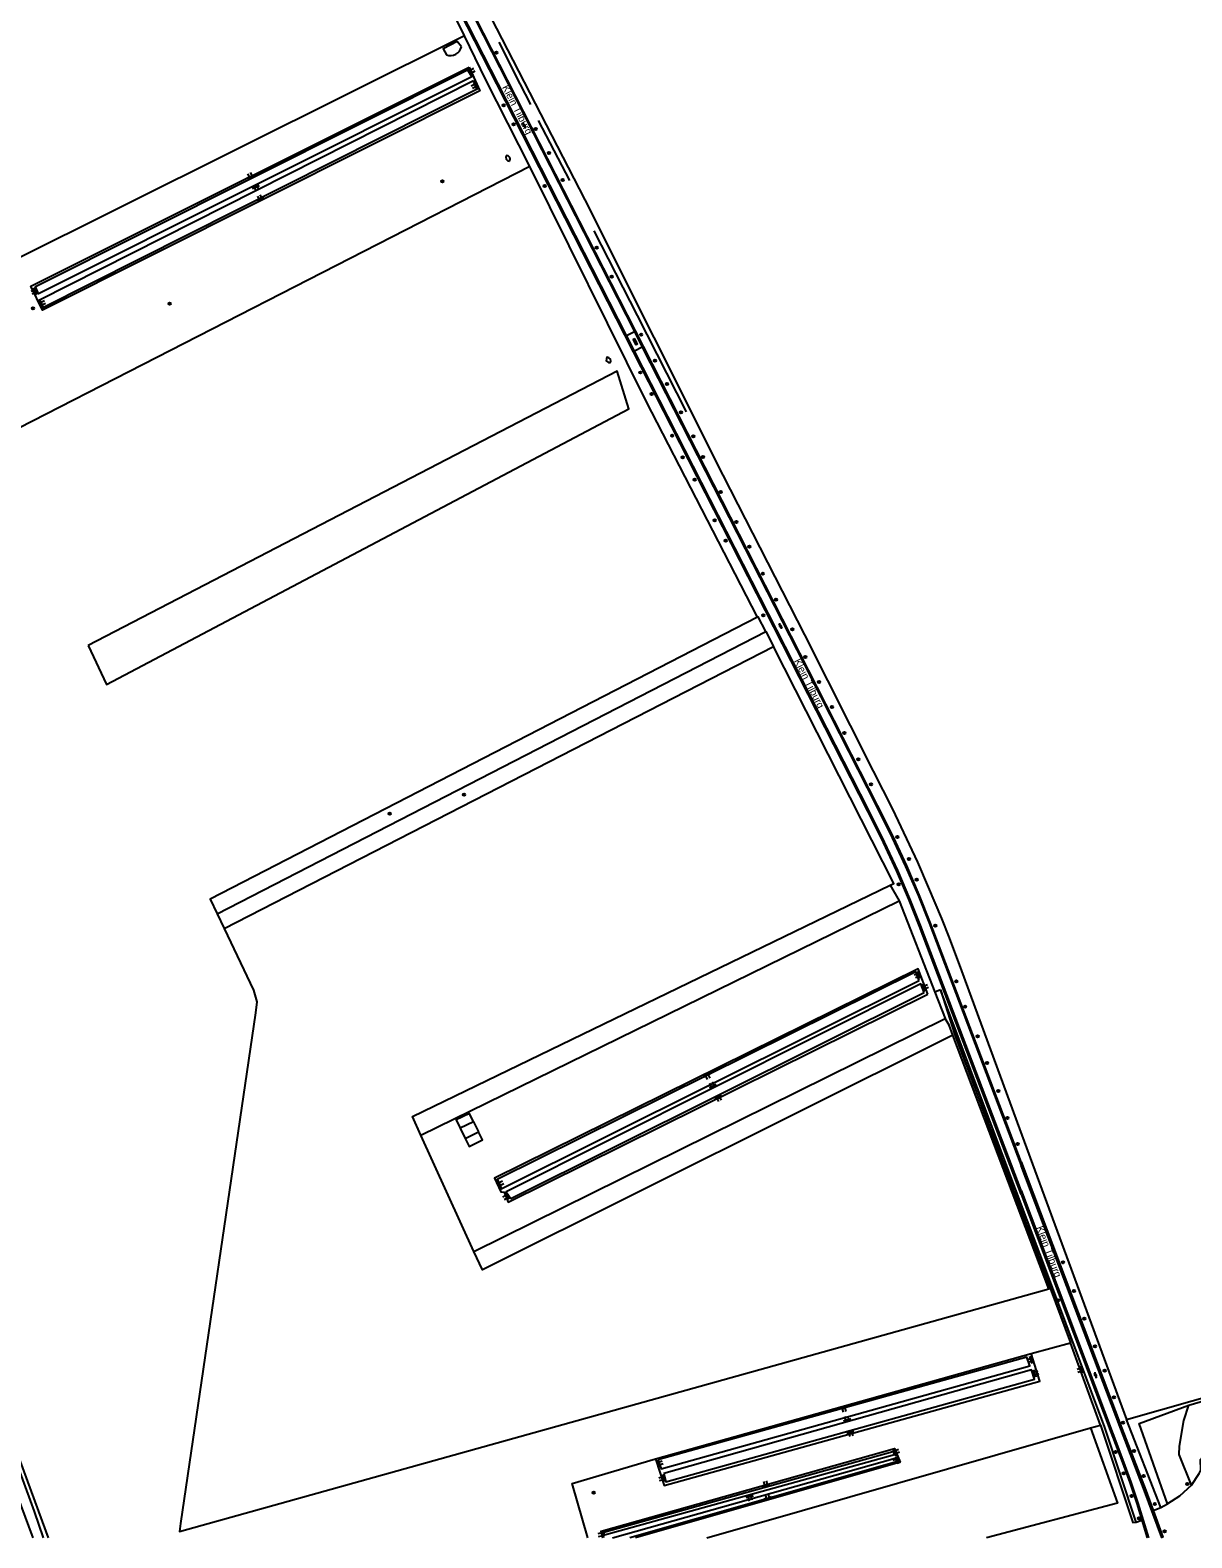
# Model space of a CAD drawing. Extents: x 124000 to 129000, y 395500 to 397503.
# Drawn here: x 126659 to 127059, y 395500 to 396018 of the extents above; entities that cross this region are included whole.
import ezdxf

# ---------------------------------------------------------------- set-up
doc = ezdxf.new("R2010")
doc.units = 0
for name, color, linetype in [('gg-afsc-draadraster', 7, 'Continuous'), ('gg-anno-openbare ruimte label', 7, 'Continuous'), ('gg-bbg-bijgebouw', 7, 'Continuous'), ('gg-bbg-luifel en loopbrug', 7, 'Continuous'), ('gg-knt-bovenkant onderkant talud', 7, 'Continuous'), ('gg-knt-verharding', 7, 'Continuous'), ('gg-kntw-bovenkant insteek waterloop', 7, 'Continuous'), ('gg-kntw-midden sloot', 7, 'Continuous'), ('gg-kntw-waterlijn', 7, 'Continuous'), ('gt-grn-groengrens', 7, 'Continuous'), ('gt-grn-groengrens NZ', 7, 'Continuous'), ('gt-grn-weggrens', 7, 'Continuous'), ('gt-symb-boom', 7, 'Continuous'), ('gt-symb-gesloten verharding', 7, 'Continuous'), ('gt-symb-klinker verharding', 7, 'Continuous'), ('gt-symb-talud symbool', 7, 'Continuous')]:
    doc.layers.add(name, color=color, linetype=linetype)

# ---------------------------------------------------------------- blocks, each defined once
blk = doc.blocks.new('gt0-BOOM')
at = {"layer": 'gt-symb-boom'}
for radius in [0.4, 0.2]:
    blk.add_circle((0, 0), radius, dxfattribs=at)
blk = doc.blocks.new('gt0-TALUD_1')
at = {"layer": 'gt-symb-talud symbool'}
for p, q in [((-1, -1), (-1, 0)), ((-0.5, -2), (-0.5, 0)), ((0, -1), (0, 0)), ((0.5, -2), (0.5, 0)), ((1, -1), (1, 0))]:
    blk.add_line(p, q, dxfattribs=at)
blk = doc.blocks.new('gt0-GESVH1')
at = {"layer": 'gt-symb-gesloten verharding'}
for p, q in [((-0.99, -0.26), (0.01, 0.24)), ((0.01, -0.26), (-0.99, 0.24)), ((0.01, 0.24), (1.01, -0.26)), ((1.01, 0.24), (0.01, -0.26))]:
    blk.add_line(p, q, dxfattribs=at)
blk = doc.blocks.new('gt0-KL1')
at = {"layer": 'gt-symb-klinker verharding'}
for p, q in [((-1.15, 0.3), (1.15, 0.3)), ((-1, -0.3), (-1, 0.3)), ((-0.5, 0.3), (-0.5, 0.45)), ((0, -0.3), (0, 0.3)), ((0.5, 0.3), (0.5, 0.45)), ((1, -0.3), (1, 0.3)), ((-1.15, -0.3), (1.15, -0.3)), ((-0.5, -0.45), (-0.5, -0.3)), ((0.5, -0.45), (0.5, -0.3))]:
    blk.add_line(p, q, dxfattribs=at)

msp = doc.modelspace()

# ---------------------------------------------------------------- linework, layer by layer
at = {"layer": 'gg-afsc-draadraster'}
for p, q in [((126726.02, 395709.53), (126914.84, 395806.46)), ((127009.5, 395585.57), (126976.53, 395672.83)), ((126811.92, 395598.36), (126793.63, 395638.4)), ((127036.25, 395540.67), (127076.4, 395552.07))]:
    msp.add_line(p, q, dxfattribs=at)
for points in [[(126954.95, 395724.35), (126956.26, 395724.99), (126914.84, 395806.46)], [(126793.63, 395638.4), (126790.8, 395644.81), (126954.95, 395724.35)], [(126726.02, 395709.53), (126736.15, 395688.3), (126737.27, 395684.29), (126736.88, 395680.43), (126711.09, 395504.92), (126710.75, 395502.07), (127009.5, 395585.57)], [(126976.53, 395672.83), (126814.87, 395592.14), (126811.92, 395598.36)]]:
    msp.add_lwpolyline(points, dxfattribs=at)
at = {"layer": 'gg-bbg-bijgebouw'}
for p, q in [((126811.81, 395643.05), (126807.22, 395640.8)), ((126808.94, 395637.3), (126813.53, 395639.55))]:
    msp.add_line(p, q, dxfattribs=at)
for points in [[(126811.81, 395643.05), (126810.44, 395645.84), (126805.82, 395643.65), (126807.22, 395640.8)], [(126808.94, 395637.3), (126810.28, 395634.57), (126814.89, 395636.76), (126813.53, 395639.55)]]:
    msp.add_lwpolyline(points, dxfattribs=at)
at = {"layer": 'gg-bbg-luifel en loopbrug'}
for p, q in [((126811.81, 395643.05), (126813.53, 395639.55)), ((126807.22, 395640.8), (126808.94, 395637.3))]:
    msp.add_line(p, q, dxfattribs=at)
at = {"layer": 'gg-knt-bovenkant onderkant talud'}
for p, q in [((127027.25, 395538.72), (127016.92, 395566.99)), ((126874.27, 395527.09), (127003.43, 395563.28))]:
    msp.add_line(p, q, dxfattribs=at)
for points in [[(126810.25, 396005.71), (126813.99, 395997.49), (126663.62, 395922.06), (126659.57, 395930.41), (126810.25, 396005.71)], [(126809.65, 396004.72), (126811.16, 396002.34), (126662.25, 395927.7), (126661.2, 395930.22), (126809.65, 396004.72)], [(126811.81, 396001.06), (126813, 395998.09), (126663.76, 395922.95), (126662.35, 395925.52), (126811.81, 396001.06)], [(126967.96, 395686.95), (126964.6, 395695.65), (126819, 395623.59), (126821.21, 395618.94), (126822.25, 395618.85), (126823.67, 395615.36), (126967.96, 395686.95)], [(126964.89, 395691.55), (126963.82, 395694.59), (126819.86, 395623.12), (126821.32, 395619.94), (126964.89, 395691.55)], [(126966.71, 395687.42), (126965.52, 395690.46), (126823.03, 395618.96), (126824.58, 395616.59), (126966.71, 395687.42)], [(126972.32, 395688.38), (126977.25, 395672.91), (127009.98, 395585.75)], [(127039.52, 395505.39), (127028.82, 395537.85), (127010.82, 395586), (126972.32, 395688.38)], [(127009.98, 395585.75), (127009.98, 395585.75), (127016.92, 395566.99)], [(126874.27, 395527.09), (126877.27, 395517.98), (127006.42, 395553.86), (127003.43, 395563.28)], [(126875.16, 395526.79), (126876.28, 395523.68), (127002.96, 395559.14), (127001.93, 395562.1), (126875.16, 395526.79)], [(126877.14, 395522.02), (126877.84, 395519.22), (127004.55, 395554.52), (127003.52, 395557.74), (126877.14, 395522.02)], [(127027.25, 395538.72), (127038.42, 395505.21), (127039.52, 395505.39)], [(126856.31, 395500), (126855.62, 395502.29), (126956.47, 395530.72), (126958.38, 395525.91), (126867.44, 395500)], [(126856.74, 395500.82), (126856.51, 395501.87), (126955.92, 395529.64), (126956.42, 395528.49), (126856.74, 395500.82)], [(126859.59, 395500), (126956.69, 395527.31), (126957.19, 395526.11), (126865.53, 395500)]]:
    msp.add_lwpolyline(points, dxfattribs=at)
at = {"layer": 'gg-knt-verharding'}
for p, q in [((126823.63, 396000), (126867.07, 395914.76)), ((126864.32, 395913.35), (126867.07, 395914.76)), ((126867.06, 395907.99), (126864.32, 395913.35)), ((126867.07, 395914.76), (126869.79, 395909.41)), ((126869.79, 395909.41), (126867.06, 395907.99)), ((127041.52, 395505.99), (127043.33, 395500)), ((127048.28, 395500), (127048.3, 395500.01)), ((127048.3, 395500.01), (127048.35, 395500.02)), ((127048.3, 395500.01), (127048.3, 395500))]:
    msp.add_line(p, q, dxfattribs=at)
for points in [[(126703.21, 396235.33), (126720.5, 396201.9), (126732.37, 396178.75), (126801.05, 396044.35), (126823.63, 396000)], [(126870.15, 395909.59), (126801.43, 396044.48), (126720.87, 396202.08)], [(126866.72, 395907.82), (126819.75, 396000), (126794.42, 396049.62), (126770.73, 396095.86), (126742.38, 396151.54)], [(126864.32, 395913.35), (126849.75, 395941.89), (126820.21, 396000), (126794.79, 396049.81), (126771.05, 396096.11), (126742.75, 396151.65)], [(127000, 395618.17), (126965.03, 395710.31), (126961.37, 395719.61), (126957.24, 395729.17), (126952.63, 395739.06), (126947.31, 395749.8), (126879.78, 395882.18), (126866.72, 395907.82)], [(127000, 395619.35), (126965.41, 395710.47), (126961.76, 395719.74), (126957.58, 395729.44), (126953.01, 395739.22), (126947.65, 395750.04), (126867.06, 395907.99)], [(126869.79, 395909.41), (126905.15, 395840.02), (126927.99, 395795.44), (126950.32, 395751.6), (126955.72, 395740.7), (126960.3, 395730.86), (126964.62, 395720.97), (126968.39, 395711.41), (127000, 395628.01)], [(127000, 395629.23), (126968.77, 395711.55), (126965, 395721.1), (126960.7, 395730.98), (126956.08, 395740.87), (126950.68, 395751.78), (126882.29, 395885.77), (126870.15, 395909.59)], [(127000, 395629.23), (127034.62, 395537.57), (127042.8, 395516.21), (127045.33, 395509.32)], [(127048.35, 395500.02), (127042.4, 395516.1), (127034.24, 395537.39), (127000, 395628.01)], [(127000, 395619.35), (127034.84, 395526.86), (127037.68, 395519.14), (127040.12, 395511.86), (127043.82, 395500)], [(127000, 395618.17), (127030.94, 395536.1), (127034.44, 395526.77), (127037.32, 395518.92), (127039.78, 395511.74), (127041.52, 395505.99)], [(127045.33, 395509.32), (127048.71, 395500.15), (127048.35, 395500.02)]]:
    msp.add_lwpolyline(points, dxfattribs=at)
at = {"layer": 'gg-kntw-bovenkant insteek waterloop'}
msp.add_lwpolyline([(126626.44, 395606.28), (126646.15, 395552.5), (126665.56, 395500)], dxfattribs=at)
at = {"layer": 'gg-kntw-midden sloot'}
for p, q in [((126820.5, 396014.31), (126827.7, 396000)), ((126827.7, 396000), (126831.3, 395992.86)), ((126833.96, 395987.35), (126844.8, 395966.73))]:
    msp.add_line(p, q, dxfattribs=at)
msp.add_lwpolyline([(126853.13, 395949.38), (126868.02, 395920.32), (126884.88, 395887.2)], dxfattribs=at)
at = {"layer": 'gg-kntw-waterlijn'}
msp.add_lwpolyline([(126660.4, 395500), (126621.27, 395605.24), (126620.28, 395607.49), (126619.19, 395609.18), (126599.63, 395634.63), (126595.98, 395639.86), (126595.97, 395640.76), (126596.45, 395641.85), (126597.38, 395642.32), (126598.31, 395642.41), (126598.99, 395642.04), (126621.37, 395612.26), (126623.4, 395609.19), (126625.11, 395605.18), (126643.23, 395556.76), (126660.79, 395508.97), (126663.9, 395500)], dxfattribs=at)
at = {"layer": 'gt-grn-groengrens'}
for p, q in [((126808.63, 396016.44), (126651.9, 395938.33)), ((126723.61, 395714.58), (126912.23, 395811.57)), ((126912.23, 395811.57), (126914.84, 395806.46)), ((126954.95, 395724.35), (126958.11, 395718.94)), ((126723.61, 395714.58), (126726.02, 395709.53)), ((126793.63, 395638.4), (126958.11, 395718.94)), ((126958.11, 395718.94), (126970.36, 395687.61)), ((126970.36, 395687.61), (126973.91, 395678.54)), ((126811.92, 395598.36), (126973.91, 395678.54)), ((127003.43, 395563.28), (127016.92, 395566.99)), ((127057.64, 395545.62), (127076.66, 395551.15)), ((126891.93, 395500), (127023.81, 395537.73)), ((127023.81, 395537.73), (127027.25, 395538.72)), ((127048.03, 395510.35), (127036.25, 395540.67)), ((127045.33, 395509.32), (127048.03, 395510.35)), ((127048.03, 395510.35), (127050.33, 395511.62)), ((127039.52, 395505.39), (127041.52, 395505.99))]:
    msp.add_line(p, q, dxfattribs=at)
for points in [[(126747.44, 396158.87), (126804.46, 396048.68), (126849.98, 395960.03), (126897.51, 395865.41), (126925.49, 395810.42), (126949.11, 395763.57), (126955.76, 395750.52), (126964.33, 395732.29), (126968.05, 395723.74), (126972.66, 395712.9), (126975.3, 395706.31), (126979.51, 395694.89), (126999.42, 395640.58), (127036.25, 395540.67)], [(126808.63, 396016.44), (126803.18, 396027.6), (126769.53, 396092.2), (126743.11, 396143.03)], [(126831.14, 395971.52), (126816.04, 396001.3), (126808.63, 396016.44)], [(126807.58, 396012.68), (126806.15, 396014.47), (126801.36, 396012.01), (126802.53, 396009.92)], [(126824.11, 395973.39), (126824.37, 395974.01), (126824.24, 395974.64), (126823.71, 395975.18), (126823.15, 395975.27), (126822.92, 395974.69), (126822.99, 395974.05), (126823.53, 395973.52), (126824.11, 395973.39)], [(126831.14, 395971.52), (126645.72, 395876.57), (126625.28, 395920.24)], [(126909.36, 395816.54), (126871.07, 395890.86), (126831.35, 395971.1), (126831.14, 395971.52)], [(126858.69, 395903.97), (126858.92, 395904.54), (126858.8, 395905.31), (126858.24, 395905.71), (126857.64, 395905.9), (126857.46, 395905.39), (126857.4, 395904.66), (126858.11, 395904.12), (126858.69, 395903.97)], [(126679.37, 395806.78), (126685.61, 395793.43), (126865.19, 395888.16), (126861.17, 395901.1), (126679.37, 395806.78)], [(126909.36, 395816.54), (126721.2, 395719.62), (126723.61, 395714.58)], [(126912.23, 395811.57), (126909.62, 395816.67), (126909.36, 395816.54)], [(126976.53, 395672.83), (126975.28, 395676.22), (126973.91, 395678.54)], [(127050.33, 395511.62), (127040.56, 395539.3), (127057.64, 395545.62)], [(127058.54, 395518.11), (127054.34, 395528.6), (127054.38, 395531.47), (127055.89, 395540.28), (127057.64, 395545.62)], [(127023.81, 395537.73), (127033.12, 395511.88), (126988.1, 395500)], [(127058.54, 395518.11), (127061.14, 395522.05), (127061.79, 395523.19), (127061.67, 395526.84), (127068.1, 395534.4)], [(126851.1, 395500), (126845.65, 395518.66), (126874.27, 395527.09)], [(127058.54, 395518.11), (127054.44, 395514.28), (127050.33, 395511.62)]]:
    msp.add_lwpolyline(points, dxfattribs=at)
msp.add_arc((126803.85, 396013.5), 3.82, 249.883, 347.5876, dxfattribs=at)
at = {"layer": 'gt-grn-groengrens NZ'}
for p, q in [((126972.32, 395688.38), (126970.36, 395687.61)), ((127009.98, 395585.75), (127009.5, 395585.57))]:
    msp.add_line(p, q, dxfattribs=at)
at = {"layer": 'gt-grn-weggrens'}
for p, q in [((126867.06, 395907.99), (126866.72, 395907.82)), ((126870.15, 395909.59), (126869.79, 395909.41))]:
    msp.add_line(p, q, dxfattribs=at)

# ---------------------------------------------------------------- block references
at = {"layer": 'gt-symb-boom'}
for p in [(126819.64, 396010.67), (126822.18, 395992.54), (126825.53, 395986.05), (126833.16, 395984.41), (126837.71, 395976.14), (126801.06, 395966.42), (126836.25, 395964.82), (126842.44, 395966.92), (126854.14, 395943.65), (126859.26, 395933.67), (126660.32, 395922.79), (126707.28, 395924.33), (126869.39, 395913.73), (126869.14, 395900.68), (126874.12, 395904.71), (126878.26, 395896.77), (126872.98, 395893.27), (126883.07, 395887.02), (126880.05, 395878.91), (126887.31, 395878.76), (126883.68, 395871.52), (126890.63, 395871.58), (126887.83, 395863.79), (126896.73, 395859.64), (126894.7, 395849.85), (126902.15, 395849.27), (126898.45, 395842.87), (126906.59, 395840.79), (126911.21, 395831.47), (126915.73, 395822.57), (126911.33, 395817.14), (126921.37, 395812.36), (126925.77, 395802.83), (126930.52, 395794.24), (126934.95, 395785.66), (126939.26, 395776.66), (126943.99, 395767.64), (126808.53, 395755.47), (126948.43, 395759.06), (126782.96, 395748.97), (126957.47, 395740.95), (126961.4, 395733.33), (126957.94, 395724.71), (126964.1, 395726.28), (126970.49, 395710.47), (126977.7, 395691.26), (126980.76, 395682.62), (126985.03, 395672.36), (126988.28, 395663.19), (126992.15, 395653.57), (126995.3, 395644.3), (126998.76, 395635.33), (127014.39, 395594.74), (127018.13, 395584.83), (127012.65, 395581.65), (127021.69, 395575.33), (127025.43, 395565.79), (127028.73, 395557.39), (127031.88, 395548.22), (127035.05, 395539.58), (127032.47, 395529.46), (127038.8, 395529.76), (127035.26, 395522.09), (127042.08, 395521.22), (127057.12, 395518.51), (126853.1, 395515.44), (127037.94, 395514.31), (127045.95, 395511.6), (127040.5, 395506.63), (127049.3, 395502.21)]:
    msp.add_blockref('gt0-BOOM', p, dxfattribs=at)
at = {"layer": 'gt-symb-gesloten verharding'}
for p, rotation in [((126829.21, 395985.57), 116.92362535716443), ((126917.24, 395813.48), 117.07775140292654), ((127025.6, 395555.87), -69.33669709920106)]:
    msp.add_blockref('gt0-GESVH1', p, dxfattribs=dict(at, rotation=rotation))
at = {"layer": 'gt-symb-klinker verharding', "rotation": 117.38497058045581}
msp.add_blockref('gt0-KL1', (126867.38, 395911.25), dxfattribs=at)
at = {"layer": 'gt-symb-talud symbool'}
for p, xscale, yscale, rotation in [((126810.29, 396003.71), 1.0001249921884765, 1.0001249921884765, 122.33937707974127), ((126812.97, 395999.72), 1.0001139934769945, 1.0001139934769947, -64.40857586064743), ((126735.43, 395967.47), 1.0004184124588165, 1.0004184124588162, -153.33249782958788), ((126736.7, 395965.02), 0.9999699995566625, 0.9999699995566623, 26.616299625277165), ((126738.81, 395959.78), 0.9999699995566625, 0.9999699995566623, -153.38370037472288), ((126661.73, 395928.96), 1.0002324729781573, 1.0002324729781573, -67.48588735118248), ((126662.68, 395924.01), 0.9995849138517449, 0.9995849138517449, 115.92418551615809), ((126965.32, 395693.81), 1.000044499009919, 1.000044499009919, -68.90078774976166), ((126966.11, 395688.94), 0.9996284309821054, 0.9996284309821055, 111.35437736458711), ((126891.8, 395659.62), 0.9999759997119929, 0.9999759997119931, 26.360058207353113), ((126894.27, 395654.71), 0.9999699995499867, 0.9999699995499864, -153.3837003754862), ((126895.65, 395652), 0.9999704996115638, 0.9999704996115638, 26.488178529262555), ((126820.11, 395621.27), 0.9997249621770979, 0.999724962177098, 115.4116007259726), ((126823.81, 395617.78), 0.9995999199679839, 0.9995999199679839, -56.75506275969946), ((127004.02, 395561.4), 0.999706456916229, 0.9997064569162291, -72.41690287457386), ((127021.27, 395558.04), 0.999706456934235, 0.9997064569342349, -72.41690287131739), ((127004.01, 395556.21), 1.0000089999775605, 1.00000899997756, 107.63771555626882), ((126938.85, 395545.18), 1.0001344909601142, 1.0001344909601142, 15.66210634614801), ((126940.33, 395539.88), 0.9997139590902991, 0.9997139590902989, -164.21205294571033), ((126941.19, 395536.87), 0.9995964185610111, 0.9995964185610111, 15.551724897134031), ((126957.98, 395526.91), 1.0001619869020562, 1.0001619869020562, -68.41134771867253), ((126956.17, 395529.06), 1.0000449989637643, 1.0000449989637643, 113.51455667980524), ((126874.89, 395525.21), 1.0002344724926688, 1.0002344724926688, 108.23569145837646), ((126877.49, 395520.62), 0.9997319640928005, 0.9997319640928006, -75.9915565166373), ((126912.47, 395517.5), 0.9998649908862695, 0.9998649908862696, -164.3930695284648), ((126906.58, 395514.66), 1.0002924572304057, 1.0002924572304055, 15.481185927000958), ((126913.07, 395513), 1.0002599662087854, 1.0002599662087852, -164.10181291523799), ((126856.63, 395501.35), 1.00016248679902, 1.00016248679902, -77.64517308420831)]:
    msp.add_blockref('gt0-TALUD_1', p, dxfattribs=dict(at, xscale=xscale, yscale=yscale, rotation=rotation))

# ---------------------------------------------------------------- texts
at = {"layer": 'gg-anno-openbare ruimte label'}
for rotation, p in [(297.2, (126821.5, 395998.76)), (297, (126921.84, 395801.48)), (290.6, (127005.16, 395606.65))]:
    msp.add_text('Klein Tilburg', height=2.5, rotation=rotation, dxfattribs=at).set_placement(p)

doc.saveas('drawing.dxf')
